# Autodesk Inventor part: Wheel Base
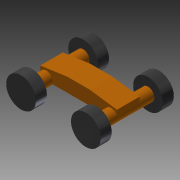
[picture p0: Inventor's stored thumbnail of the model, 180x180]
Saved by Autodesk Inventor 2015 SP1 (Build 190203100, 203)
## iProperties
Created: 2008-11
Part Number: Wheel Base
Document SubType Name: Modeling
Designer: dwoollam
Density: 7.85 g/cm^3
Material: Steel
Appearance: Plate
Mass: 1.47594e+07 g
Surface Area: 167452 cm^2
Volume: 1.88018e+06 cm^3
Dwg_Category: Clearance_Mewp
INSTALLATION: False
CIVIL_WORK: False
EARTHING: False
MOUNTING: False
Author: dwoollam
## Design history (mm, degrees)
sketch "Sketch1"
  geometry: L1 (1017.5, 1145)-(1482.5, 1145); L2 (1482.5, 1145)-(1482.5, 800); L3 (1217.5, 800)-(1217.5, 0); L4 (1017.5, 0)-(1217.5, 0); L5 (1017.5, 0)-(1017.5, 800); L6 (1482.5, 800)-(1017.5, 800); L7 (1017.5, 800)-(1017.5, 1145); L8 (1017.5, 800)-(1217.5, 800); 1 further point
  constraints: 16 end point, 3 vertical, 2 perpendicular, 1 collinear, 1 horizontal, 1 horizontal alignment, 1 point on line
  dimensions: "d0" = 345 distance of L1.end L2.end; "d3" = 465 distance of L1.start L1.end; "d4" = 200 distance of L4.start L3.end; "d8" = 1145 distance between parallel lines of L1 L4; "d10" = 1017.5 distance of point (0, 0) L4.start
revolve "Axel_1" stored, may be unused: angle "d11" = 90 deg
revolve "Wheel" stored, may be unused: angle "d12" = 90 deg
mirror "Mirror1"
mirror "Mirror2"
pattern_linear "Rectangular Pattern1"
pattern_linear "Rectangular Pattern2"
sketch "Sketch2"
  geometry: L1 (1200, -75)-(-1200, -75); L2 (-1200, -75)-(-1200, 240); L3 (-1200, 240)-(-355, 360); L4 (-355, 360)-(355, 360); L5 (355, 360)-(1200, 240); L6 (1200, 240)-(1200, -75); C1 r 200 at (1012.5, 0) reference; C2 r 465 at (1012.5, 0) reference; C3 r 132.5 at (1012.5, 0) reference; 3 further points
  constraints: 12 end point, 3 parallel, 2 midpoint, 2 vertical alignment, 1 horizontal, 1 perpendicular
  dimensions: "d19" = 2400 distance of L1.start L1.end; "d20" = 710 distance of L3.end L4.end; "d21" = 315 distance of L5.end L1.start; "d22" = 435 distance between parallel lines of L1 L4; "d23" = 75 distance from line of L1 C1.centre
extrude "Wheel Base" join sketch "Sketch2" stored distance "d24" = 710; taper "d25" = 0 deg
workaxis "Work Axis1"
workplane "Work Plane1"
sketch "Constraint Sketch"
  geometry: L1 (0, 0)-(0, 710) reference; L2 (1659.19, 710)-(1659.19, 0) reference; L3 (-650.405, -790)-(279.595, -790) reference; L4 (-650.405, 1500)-(279.595, 1500) reference; L5 (1379.595, 1500)-(2309.595, 1500) reference; L6 (1379.595, -790)-(2309.595, -790) reference; L7 (1659.19, 355)-(0, 355); C1 r 100 at (-185.405, 455); C2 r 100 at (-185.405, 255); C3 r 100 at (1844.595, 255); C4 r 100 at (1844.595, 455); 3 further points
  constraints: 4 centre point, 4 equal radius, 4 midpoint, 4 vertical alignment, 2 end point, 2 horizontal alignment
  dimensions: "d29" = 200 diameter of C1; "d30" = 100 distance from line of L7 C2.centre (= 0.5 x d29)
extrude_surface "ExtrusionSrf2" dims "d31" = 150, "d32" = 0
extrude_surface "ExtrusionSrf3" dims "d33" = 150, "d34" = 0
body "Solid1"
node "Projected Loop1"
body "Srf1"
body "Srf2"
